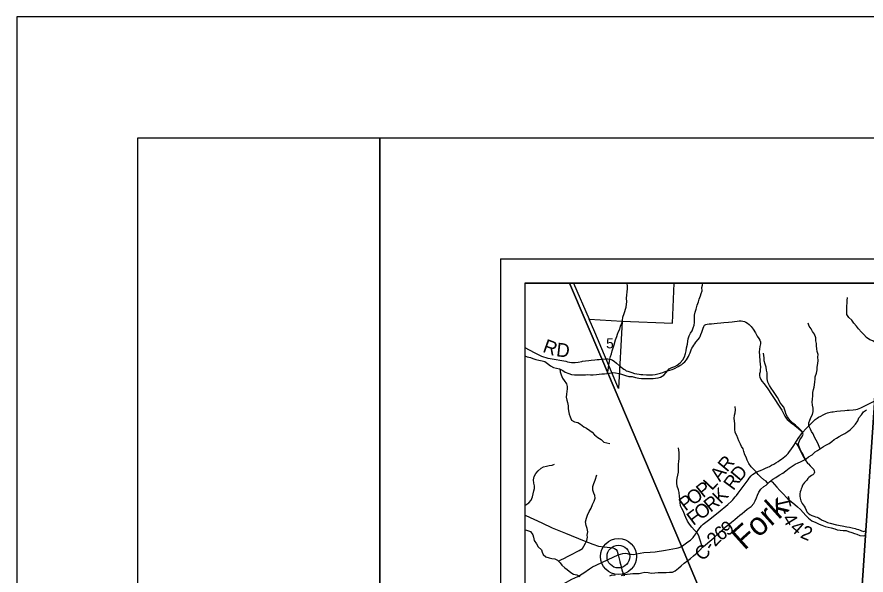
# Model space of a CAD drawing. Extents: x 0 to 34, y 0 to 22.
# Drawn here: x 0 to 3.511, y 19.693 to 22 of the extents above; entities that cross this region are included whole.
import ezdxf

# ---------------------------------------------------------------- set-up
doc = ezdxf.new("R2010")
doc.units = 0
for name, color, linetype in [('GM_X_County_Road', 7, 'Continuous'), ('GM_X_County_Road_Text', 7, 'Continuous'), ('GM_X_Minor_River', 7, 'Continuous'), ('GM_X_Minor_River_Text', 7, 'Continuous'), ('GM_X_Section', 7, 'Continuous'), ('GM_X_Section_Text', 7, 'Continuous'), ('GM_X_State_Route', 7, 'Continuous'), ('GM_X_Township_Road', 7, 'Continuous'), ('GM_X_Township_Road_Text', 7, 'Continuous'), ('GM_X_Unincorporated', 7, 'Continuous'), ('GM_X_Unincorporated_Location', 7, 'Continuous'), ('SH_Border', 7, 'Continuous'), ('SH_Cut_Line', 7, 'Continuous'), ('SH_Data', 7, 'Continuous')]:
    doc.layers.add(name, color=color, linetype=linetype)

msp = doc.modelspace()

# ---------------------------------------------------------------- linework, layer by layer
at = {"layer": 'GM_X_County_Road'}
for points in [[(2.7739, 19.8298), (2.7851, 19.8379), (2.7904, 19.8427), (2.7958, 19.8477), (2.7994, 19.8521), (2.803, 19.8578), (2.8067, 19.8636), (2.8095, 19.8687), (2.8193, 19.8833), (2.8246, 19.8903), (2.8306, 19.8969), (2.8369, 19.9032), (2.8588, 19.9195), (2.8997, 19.952), (2.9396, 19.985), (2.9543, 19.9983), (2.96, 20.0037), (2.9648, 20.0096), (2.9696, 20.0159), (2.9749, 20.0226), (2.9827, 20.0323), (3.023, 20.0866), (3.0278, 20.0931), (3.0364, 20.103), (3.0419, 20.1082), (3.0477, 20.113), (3.0538, 20.117), (3.0603, 20.1203), (3.0662, 20.1222), (3.075, 20.1258), (3.0863, 20.1303), (3.0951, 20.1346), (3.1045, 20.139), (3.1112, 20.1423), (3.1197, 20.1469), (3.1294, 20.1519), (3.1384, 20.1572), (3.1479, 20.1629), (3.1545, 20.1674), (3.1614, 20.1727), (3.1685, 20.1779), (3.1752, 20.1831), (3.1819, 20.189), (3.1884, 20.1961), (3.1945, 20.2032), (3.1999, 20.2105), (3.2126, 20.2285), (3.2196, 20.2395), (3.2308, 20.2572), (3.2475, 20.282), (3.2635, 20.2983), (3.2932, 20.3292), (3.3011, 20.3364), (3.3086, 20.3416), (3.3149, 20.3453), (3.3233, 20.3506), (3.3342, 20.3561), (3.3396, 20.3586), (3.3446, 20.3609), (3.3513, 20.3634), (3.3626, 20.3666), (3.3689, 20.3674), (3.375, 20.3682), (3.3903, 20.3703), (3.4054, 20.372), (3.4234, 20.3735), (3.4328, 20.3743), (3.4417, 20.3744), (3.4575, 20.3756), (3.4686, 20.377), (3.4755, 20.3785), (3.4826, 20.381), (3.4893, 20.3844), (3.5465, 20.4139)], [(2.4861, 19.7772), (2.5054, 19.7827), (2.5157, 19.7836), (2.5234, 19.782), (2.5314, 19.7801), (2.5403, 19.779), (2.5509, 19.7784), (2.5617, 19.7802), (2.5926, 19.786), (2.6179, 19.7872), (2.6393, 19.7886), (2.682, 19.7958), (2.7265, 19.8042), (2.7338, 19.806), (2.7416, 19.8088), (2.7475, 19.8116), (2.757, 19.8176), (2.7739, 19.8298)], [(2.1, 19.577), (2.1629, 19.6015), (2.1807, 19.6078), (2.1964, 19.6157), (2.2092, 19.6227), (2.2498, 19.6515), (2.2594, 19.6574), (2.2946, 19.6756), (2.3185, 19.6871), (2.3444, 19.7028), (2.3667, 19.7187), (2.3804, 19.7267), (2.3947, 19.7344), (2.4447, 19.7581), (2.4861, 19.7772)]]:
    msp.add_lwpolyline(points, dxfattribs=at)
at = {"layer": 'GM_X_Minor_River'}
for points in [[(2.4417, 20.5269), (2.4447, 20.5405), (2.4455, 20.55), (2.4467, 20.5621), (2.4495, 20.5754), (2.4511, 20.5852), (2.4546, 20.597), (2.4581, 20.6075), (2.4612, 20.6204), (2.4647, 20.6318), (2.4697, 20.6446), (2.4752, 20.6651), (2.4806, 20.6791), (2.4837, 20.6889), (2.4879, 20.6995), (2.4926, 20.7101), (2.4961, 20.7226), (2.5007, 20.7347), (2.5034, 20.7449), (2.5058, 20.7596), (2.5101, 20.774), (2.5186, 20.8005), (2.5206, 20.8126), (2.5211, 20.8221), (2.5204, 20.838), (2.5217, 20.8498), (2.5233, 20.8634), (2.5242, 20.8763), (2.5239, 20.8877), (2.5236, 20.898), (2.5239, 20.9)], [(2.558, 20.51), (2.5708, 20.5073), (2.5829, 20.5061), (2.5969, 20.5056), (2.6072, 20.5059), (2.62, 20.5054), (2.631, 20.5057), (2.6408, 20.5064), (2.6507, 20.5078), (2.6613, 20.5111), (2.675, 20.5198), (2.6838, 20.5307), (2.6972, 20.5454), (2.7078, 20.551), (2.7203, 20.5554), (2.7299, 20.561), (2.7428, 20.5708), (2.7527, 20.5825), (2.76, 20.5946), (2.7639, 20.6093), (2.767, 20.6203), (2.769, 20.6324), (2.7722, 20.6472), (2.7742, 20.6601), (2.7754, 20.6695), (2.7793, 20.6824), (2.7854, 20.6926), (2.7912, 20.7028), (2.7962, 20.7149), (2.7997, 20.7259), (2.802, 20.7376), (2.8021, 20.7471), (2.8018, 20.7566), (2.8015, 20.7676), (2.8046, 20.7804), (2.8081, 20.7925), (2.8124, 20.8088), (2.8182, 20.8224), (2.8213, 20.833), (2.8267, 20.847), (2.8295, 20.8569), (2.8326, 20.8686), (2.8319, 20.8819), (2.8339, 20.8917), (2.8354, 20.9)], [(3.563, 20.6475), (3.5501, 20.6536), (3.5384, 20.6616), (3.5263, 20.6655), (3.5128, 20.6751), (3.5019, 20.6873), (3.4918, 20.6977), (3.479, 20.7114), (3.4707, 20.7213), (3.4602, 20.7339), (3.4516, 20.7469), (3.4396, 20.7584), (3.4318, 20.7706), (3.4311, 20.7827), (3.4312, 20.7956), (3.4309, 20.8059), (3.4321, 20.8165), (3.433, 20.8286), (3.4338, 20.8411)], [(3.3217, 20.2151), (3.3165, 20.2246), (3.3117, 20.2379), (3.3046, 20.2505), (3.2983, 20.2634), (3.292, 20.2771), (3.2849, 20.2866), (3.2808, 20.2965), (3.2748, 20.3095), (3.2749, 20.3227), (3.278, 20.3333), (3.2834, 20.347), (3.2896, 20.3571), (3.2916, 20.3689), (3.2924, 20.3825), (3.2891, 20.3955), (3.2885, 20.4087), (3.2901, 20.419), (3.2906, 20.4349), (3.2914, 20.4482), (3.2934, 20.4595), (3.2962, 20.4697), (3.2977, 20.48), (3.299, 20.4921), (3.3002, 20.5035), (3.3007, 20.5129), (3.3053, 20.5281), (3.3081, 20.5417), (3.3093, 20.5527), (3.3121, 20.5675), (3.3122, 20.5807), (3.3108, 20.5944), (3.3131, 20.6042), (3.3083, 20.6179), (3.3076, 20.6278), (3.3066, 20.6403), (3.3055, 20.6502), (3.3037, 20.6612), (3.3034, 20.6741), (3.2983, 20.6882), (3.2893, 20.7), (3.2833, 20.7103), (3.2751, 20.7225), (3.2714, 20.735)], [(3.2601, 20.172), (3.2545, 20.1811), (3.2489, 20.1944), (3.243, 20.2043), (3.2381, 20.2138), (3.2333, 20.2271), (3.2322, 20.2374), (3.2376, 20.2514), (3.2442, 20.2623), (3.2511, 20.2744), (3.2466, 20.2869), (3.232, 20.3011), (3.2185, 20.313), (3.2079, 20.3214), (3.1959, 20.3329), (3.1865, 20.347), (3.1806, 20.3572), (3.1769, 20.3702), (3.1706, 20.3865), (3.1623, 20.3972), (3.1545, 20.4083), (3.1504, 20.4178), (3.1448, 20.4277), (3.1362, 20.4388), (3.1283, 20.4513), (3.1186, 20.4662), (3.1111, 20.4765), (3.1044, 20.491), (3.1019, 20.5039), (3.1019, 20.5145), (3.1017, 20.5285), (3.0999, 20.5403), (3.0977, 20.5525), (3.094, 20.5646), (3.0896, 20.5783), (3.0893, 20.5908), (3.0872, 20.6098)], [(2.1, 20.5988), (2.1101, 20.5951), (2.1229, 20.592), (2.1335, 20.5877), (2.1448, 20.5842), (2.1573, 20.5818), (2.1713, 20.5787), (2.1822, 20.5756), (2.1939, 20.5671), (2.2056, 20.5576), (2.218, 20.551), (2.2305, 20.5487), (2.2433, 20.5455), (2.2573, 20.5386), (2.2674, 20.5317), (2.2814, 20.5263), (2.2927, 20.5228), (2.3052, 20.5211), (2.3154, 20.5203), (2.3362, 20.5201), (2.3503, 20.5212), (2.3601, 20.5218), (2.3715, 20.5214), (2.382, 20.5205), (2.3968, 20.5227), (2.4071, 20.5238), (2.418, 20.5244), (2.429, 20.5255), (2.4396, 20.5265), (2.4495, 20.5283), (2.4639, 20.5298), (2.4745, 20.5297), (2.49, 20.5265), (2.5036, 20.5226), (2.5168, 20.5183), (2.5304, 20.5144), (2.544, 20.514), (2.558, 20.51)], [(2.2445, 20.5449), (2.2466, 20.5326), (2.2507, 20.5208), (2.2555, 20.5067), (2.263, 20.4972), (2.2716, 20.4842), (2.2746, 20.4728), (2.2745, 20.463), (2.2736, 20.452), (2.272, 20.4414), (2.2712, 20.4289), (2.2741, 20.4163), (2.2767, 20.4061), (2.2785, 20.3932), (2.2791, 20.3822), (2.2806, 20.3723), (2.2839, 20.3575), (2.2868, 20.3472), (2.2935, 20.3339), (2.3059, 20.3262), (2.3195, 20.3231), (2.3305, 20.3169), (2.3444, 20.3065), (2.3553, 20.3004), (2.3685, 20.2908), (2.3783, 20.2835), (2.388, 20.2721), (2.402, 20.2613), (2.4151, 20.254), (2.4268, 20.2429), (2.4389, 20.2391), (2.4514, 20.2371)], [(2.8123, 19.7852), (2.8237, 19.7961), (2.8352, 19.8078), (2.8451, 19.8168), (2.8569, 19.8262), (2.8725, 19.8405), (2.8821, 19.8476), (2.8939, 19.8597), (2.9068, 19.871), (2.9171, 19.8807), (2.9282, 19.8916), (2.9389, 19.8999), (2.9549, 19.9111), (2.9686, 19.9224), (2.9793, 19.933), (2.9895, 19.9408), (2.9991, 19.9476), (3.0086, 19.9555), (3.0196, 19.9649), (3.0352, 19.9761), (3.0463, 19.9889), (3.0521, 19.9995), (3.0579, 20.012), (3.0621, 20.0229), (3.0675, 20.0354), (3.0759, 20.0486), (3.0878, 20.0591), (3.098, 20.0651), (3.1114, 20.0779), (3.1251, 20.0892), (3.1376, 20.0959), (3.1517, 20.1057), (3.1669, 20.1146), (3.1795, 20.1233), (3.1928, 20.1345), (3.205, 20.1428), (3.2179, 20.1514), (3.2297, 20.1574), (3.2396, 20.1615), (3.2506, 20.1663), (3.2632, 20.1738), (3.2731, 20.1821), (3.2879, 20.1903), (3.3005, 20.2019), (3.3107, 20.2083), (3.3229, 20.2158), (3.3355, 20.2248), (3.345, 20.2304), (3.3587, 20.2371), (3.3697, 20.2458), (3.3792, 20.2533), (3.3887, 20.2593), (3.4001, 20.266), (3.4127, 20.2731), (3.423, 20.2783), (3.4355, 20.2866), (3.445, 20.2941), (3.4565, 20.3043), (3.4675, 20.3163), (3.4764, 20.3303), (3.481, 20.3427), (3.4917, 20.3552), (3.5009, 20.3684), (3.5131, 20.3766)], [(3.1052, 20.072), (3.0978, 20.0807), (3.0876, 20.0868), (3.0741, 20.0991), (3.0651, 20.1086), (3.0568, 20.1193), (3.0448, 20.1304), (3.0358, 20.1399), (3.026, 20.1544), (3.019, 20.1678), (3.0153, 20.1803), (3.0097, 20.1902), (3.0052, 20.2039), (3.0023, 20.2149), (2.9963, 20.2244), (2.9919, 20.234), (2.9848, 20.2477), (2.9807, 20.2595), (2.9759, 20.2697), (2.9703, 20.2823), (2.9685, 20.2956), (2.9682, 20.3066), (2.9683, 20.3176), (2.9673, 20.3301), (2.9662, 20.3403), (2.9667, 20.3536), (2.969, 20.3638), (2.971, 20.3767), (2.9696, 20.3892)], [(2.8341, 19.8067), (2.8304, 19.82), (2.8267, 19.8329), (2.8219, 19.8451), (2.8189, 19.855), (2.8129, 19.8671), (2.8021, 19.879), (2.7908, 19.8908), (2.7807, 19.9038), (2.7725, 19.9164), (2.7661, 19.9308), (2.7613, 19.9411), (2.7565, 19.9552), (2.7486, 19.9689), (2.7438, 19.9795), (2.7416, 19.9936), (2.7406, 20.008), (2.7396, 20.0179), (2.7382, 20.0342), (2.7356, 20.046), (2.7301, 20.0601), (2.7279, 20.073), (2.7287, 20.0836), (2.7299, 20.0942), (2.7323, 20.1059), (2.7347, 20.1184), (2.7355, 20.1286), (2.736, 20.1393), (2.7357, 20.151), (2.7369, 20.1631), (2.7378, 20.1753), (2.7386, 20.1863), (2.7387, 20.1999), (2.7369, 20.2094), (2.7355, 20.2193)], [(2.1, 19.9809), (2.1045, 19.9834), (2.1159, 19.9913), (2.1255, 20.0022), (2.1316, 20.0162), (2.134, 20.0295), (2.1375, 20.0412), (2.1403, 20.051), (2.1396, 20.0617), (2.1366, 20.0731), (2.1356, 20.0863), (2.1384, 20.1), (2.146, 20.1128), (2.1548, 20.1237), (2.167, 20.1343), (2.1773, 20.1406), (2.1894, 20.1436), (2.2, 20.1454), (2.2126, 20.1475), (2.2224, 20.1513)], [(2.2398, 19.7499), (2.2484, 19.7555), (2.2636, 19.7626), (2.2762, 19.7705), (2.2895, 19.7768), (2.3013, 19.782), (2.3108, 19.7873), (2.3252, 19.7951), (2.3382, 19.8034), (2.3439, 19.8132), (2.3512, 19.8256), (2.3566, 19.8366), (2.3586, 19.8491), (2.3579, 19.8586), (2.3603, 19.8722), (2.3581, 19.8851), (2.3529, 19.8973), (2.3511, 19.9125), (2.3547, 19.9288), (2.3597, 19.9409), (2.3666, 19.956), (2.3739, 19.9699), (2.3797, 19.9851), (2.387, 19.9987), (2.3909, 20.0115), (2.3895, 20.0225), (2.3846, 20.032), (2.3806, 20.0446), (2.3814, 20.0594), (2.3846, 20.0719), (2.3907, 20.0847), (2.397, 20.1074)], [(3.1153, 20.0811), (3.1224, 20.079), (3.1325, 20.0679), (3.1422, 20.0561), (3.1542, 20.0431), (3.1636, 20.0331), (3.188, 20.0083), (3.2012, 19.9968), (3.2166, 19.9842), (3.2279, 19.975), (3.2392, 19.9639), (3.2508, 19.9517), (3.2617, 19.9398), (3.2729, 19.9276), (3.2873, 19.9176), (3.3038, 19.9099), (3.317, 19.9037), (3.3276, 19.8995), (3.3416, 19.8933), (3.3544, 19.8909), (3.3673, 19.8882), (3.3812, 19.8839), (3.391, 19.8804), (3.4035, 19.878), (3.4168, 19.8772), (3.4281, 19.8771), (3.4387, 19.8736), (3.4519, 19.8686), (3.4632, 19.8654), (3.473, 19.8623), (3.4855, 19.8573), (3.5002, 19.8557), (3.5096, 19.858)], [(2.1, 19.8799), (2.1071, 19.8787), (2.1233, 19.8729), (2.1331, 19.8596), (2.1353, 19.8497), (2.1386, 19.836), (2.1479, 19.8215), (2.155, 19.8094), (2.1685, 19.7967), (2.1715, 19.7872), (2.1763, 19.7777), (2.1872, 19.7685), (2.2001, 19.7643), (2.2122, 19.7611), (2.2246, 19.7595), (2.2352, 19.7541), (2.2465, 19.7438), (2.2524, 19.7343), (2.2656, 19.7228), (2.2754, 19.7155), (2.2897, 19.704), (2.3017, 19.6971), (2.3146, 19.6936), (2.3274, 19.687)], [(2.4997, 19.6914), (2.5137, 19.6951), (2.5232, 19.6969), (2.5361, 19.6987), (2.5467, 19.6997), (2.5603, 19.6992), (2.5724, 19.6991), (2.5834, 19.7021), (2.5967, 19.7054), (2.6103, 19.7038), (2.6243, 19.7014), (2.6379, 19.7024), (2.6508, 19.7038), (2.6614, 19.7038), (2.6743, 19.704), (2.6841, 19.7043), (2.6977, 19.7046), (2.7102, 19.7056), (2.722, 19.7109), (2.735, 19.7218), (2.7468, 19.7311), (2.759, 19.7417), (2.7742, 19.7537), (2.7845, 19.7619), (2.7974, 19.7732), (2.8123, 19.7852)], [(2.4508, 19.6899), (2.4607, 19.6936), (2.4732, 19.692)]]:
    msp.add_lwpolyline(points, dxfattribs=at)
at = {"layer": 'GM_X_Section'}
msp.add_lwpolyline([(2.3659, 20.7513), (2.503, 20.7433), (2.4876, 20.4641), (2.389, 20.6968)], close=True, dxfattribs=at)
at = {"layer": 'GM_X_State_Route'}
for points in [[(2.1, 19.941), (2.1034, 19.9394), (2.1698, 19.9084), (2.2134, 19.8884), (2.2678, 19.8659), (2.3446, 19.8344), (2.3806, 19.8207), (2.4047, 19.8132), (2.4274, 19.8097), (2.4528, 19.8071), (2.4635, 19.8056), (2.4713, 19.803), (2.478, 19.7983), (2.4822, 19.7921), (2.4861, 19.7772), (2.4931, 19.7488)], [(2.4931, 19.7488), (2.4934, 19.7478), (2.4978, 19.7287), (2.5012, 19.7143), (2.5062, 19.6989), (2.5108, 19.6893)]]:
    msp.add_lwpolyline(points, dxfattribs=at)
at = {"layer": 'GM_X_Township_Road'}
for points in [[(2.4919, 20.5579), (2.5092, 20.5439), (2.5142, 20.5408), (2.519, 20.538), (2.5253, 20.5353), (2.5335, 20.5326), (2.5421, 20.5301), (2.5538, 20.5269), (2.5634, 20.5251), (2.5729, 20.5238), (2.5793, 20.5225), (2.5881, 20.5219), (2.6032, 20.5213), (2.617, 20.5207), (2.6277, 20.5205), (2.6388, 20.5217), (2.6503, 20.5244), (2.6612, 20.5278), (2.6704, 20.5309), (2.6801, 20.5345), (2.6889, 20.537), (2.6993, 20.5399), (2.7085, 20.5435), (2.7188, 20.5475), (2.7335, 20.5548), (2.7412, 20.5588), (2.7492, 20.5638), (2.7552, 20.5684), (2.7617, 20.5747), (2.7682, 20.5826), (2.7728, 20.5893), (2.7768, 20.596), (2.7801, 20.6034), (2.7835, 20.6111), (2.7879, 20.6239), (2.7908, 20.631), (2.794, 20.6364), (2.7982, 20.6434), (2.8028, 20.6492), (2.8074, 20.6559), (2.8164, 20.6664), (2.8216, 20.6731), (2.8254, 20.6792), (2.8283, 20.6869), (2.8317, 20.6972), (2.834, 20.706), (2.8367, 20.7135), (2.8398, 20.7202), (2.8427, 20.7254), (2.8482, 20.7292), (2.8538, 20.7309), (2.8622, 20.7315), (2.8719, 20.7319), (2.8832, 20.7326), (2.8949, 20.734), (2.91, 20.7355), (2.9232, 20.7367), (2.9418, 20.7388), (2.9569, 20.7403), (2.9671, 20.7411), (2.9778, 20.7426), (2.9866, 20.7434), (2.9945, 20.7434), (3.0017, 20.7424), (3.0088, 20.7407), (3.0144, 20.738), (3.0207, 20.7346), (3.028, 20.7284), (3.0352, 20.721), (3.0442, 20.7095), (3.0534, 20.6947), (3.0609, 20.6806), (3.0672, 20.6708), (3.0712, 20.6641), (3.0741, 20.6566), (3.0745, 20.6492), (3.072, 20.6383), (3.0703, 20.6262), (3.0693, 20.6153), (3.0699, 20.6011), (3.0722, 20.5772), (3.0741, 20.5525), (3.0737, 20.5412), (3.0726, 20.5336), (3.0708, 20.5251), (3.0697, 20.5173), (3.071, 20.5108), (3.0756, 20.5016), (3.0806, 20.4943), (3.089, 20.4836), (3.1041, 20.4635), (3.12, 20.4398), (3.1627, 20.3743), (3.1744, 20.3506), (3.1801, 20.3419), (3.1849, 20.3366), (3.192, 20.3301), (3.2018, 20.3224), (3.2144, 20.3123), (3.2267, 20.3033), (3.2475, 20.282)], [(2.1, 20.6334), (2.1388, 20.6126), (2.1627, 20.6004), (2.169, 20.5979), (2.1771, 20.5952), (2.1866, 20.5925), (2.1953, 20.5902), (2.2048, 20.5883), (2.2691, 20.5766), (2.2768, 20.5745), (2.285, 20.5734), (2.2933, 20.5715), (2.3011, 20.5718), (2.3084, 20.5722), (2.3199, 20.5738), (2.3359, 20.5763)], [(2.3359, 20.5763), (2.3388, 20.5768), (2.3503, 20.5782), (2.3645, 20.5805), (2.3744, 20.5816), (2.3894, 20.5828), (2.3991, 20.5837), (2.4077, 20.5847), (2.4182, 20.586), (2.4378, 20.587), (2.443, 20.5866)], [(2.443, 20.5866), (2.45, 20.5856), (2.4571, 20.5837), (2.4623, 20.5814), (2.4692, 20.5772), (2.4784, 20.5688), (2.4919, 20.5579)], [(3.2196, 20.2395), (3.2238, 20.2357), (3.2293, 20.2271), (3.251, 20.1836), (3.2572, 20.1725), (3.2615, 20.1656), (3.2661, 20.1601), (3.2693, 20.1561), (3.2724, 20.1524), (3.2799, 20.145), (3.2871, 20.1375), (3.2929, 20.1308), (3.2967, 20.1245), (3.2975, 20.1191), (3.2965, 20.1147), (3.2944, 20.1109), (3.2904, 20.1076), (3.2856, 20.1042), (3.2804, 20.1004), (3.2749, 20.0967), (3.2697, 20.0916), (3.2655, 20.086), (3.2605, 20.0801), (3.2563, 20.0755), (3.2521, 20.0707), (3.2485, 20.0651), (3.2448, 20.0548), (3.2429, 20.0491), (3.2406, 20.0445), (3.2383, 20.0366), (3.2368, 20.0295), (3.2364, 20.0198), (3.2381, 20.0104), (3.2414, 19.9999), (3.2462, 19.9895), (3.2515, 19.983), (3.255, 19.9782), (3.2594, 19.9704), (3.2634, 19.9612), (3.2663, 19.9549), (3.2718, 19.9495), (3.2783, 19.9432), (3.286, 19.9392), (3.2902, 19.9375), (3.295, 19.9359), (3.3025, 19.9338), (3.3086, 19.9319), (3.3143, 19.9294), (3.3206, 19.9252), (3.3298, 19.9204), (3.3398, 19.9162), (3.3515, 19.9107), (3.3622, 19.9076), (3.388, 19.9009), (3.4116, 19.8961), (3.4311, 19.8929), (3.442, 19.8913), (3.4539, 19.8881), (3.4665, 19.885), (3.4728, 19.8831), (3.4797, 19.8808), (3.4864, 19.8783), (3.4922, 19.8754), (3.4971, 19.8739), (3.5008, 19.8737), (3.5048, 19.8745), (3.5102, 19.8764)]]:
    msp.add_lwpolyline(points, dxfattribs=at)
at = {"layer": 'GM_X_Township_Road_Text'}
msp.add_lwpolyline([(2.7177, 20.9), (2.3012, 20.9), (2.3659, 20.7513), (2.503, 20.7433), (2.7106, 20.7339)], close=True, dxfattribs=at)
at = {"layer": 'GM_X_Unincorporated'}
for points in [[(2.2853, 20.9), (2.1, 20.9), (2.1, 14.1), (2.8399, 14.1), (2.9778, 14.1609), (3.8099, 14.5285), (4.2904, 14.7408), (4.3998, 14.7897), (4.802, 14.9692), (4.4847, 15.685), (4.2937, 16.1161), (4.0882, 16.6114), (3.972, 16.8916), (3.7367, 17.4136), (3.709, 17.484), (3.4011, 18.2653), (3.1249, 18.9173), (3.0781, 19.0279), (2.9956, 19.2227), (2.9553, 19.318), (2.7473, 19.8121), (2.418, 20.5866)], [(6.769, 20.9), (2.2853, 20.9), (2.418, 20.5866), (2.7473, 19.8121), (2.9553, 19.318), (2.9956, 19.2227), (3.0781, 19.0279), (3.1249, 18.9173), (3.4011, 18.2653), (3.4595, 19.1305), (3.4599, 19.1361), (3.5099, 19.8769), (3.5456, 20.4047), (3.5457, 20.4056), (3.5462, 20.4144), (3.5651, 20.6937), (3.8602, 20.6728), (4.3099, 20.6409), (6.6484, 20.4847), (6.6568, 20.5136)]]:
    msp.add_lwpolyline(points, close=True, dxfattribs=at)
msp.add_lwpolyline([(3.5456, 20.4047), (3.5099, 19.8769), (3.4599, 19.1361), (3.4595, 19.1305), (3.4011, 18.2653), (3.709, 17.484)], dxfattribs=at)
for radius in [0.0744, 0.0472]:
    msp.add_circle((2.487, 19.7697), radius, dxfattribs=at)
at = {"layer": 'GM_X_Unincorporated_Location'}
msp.add_line((2.487, 19.7697), (2.487, 19.7697), dxfattribs=at)
at = {"layer": 'SH_Border'}
for points in [[(0.5, 21.5), (1.5, 21.5), (1.5, 0.5), (0.5, 0.5)], [(1.5, 21.5), (33.5, 21.5), (33.5, 0.5), (1.5, 0.5)]]:
    msp.add_lwpolyline(points, close=True, dxfattribs=at)
at = {"layer": 'SH_Cut_Line'}
msp.add_lwpolyline([(0, 0), (34, 0), (34, 22), (0, 22)], close=True, dxfattribs=at)
for points in [[(4.2937, 16.1161), (4.0882, 16.6114), (3.972, 16.8916), (3.7367, 17.4136), (3.709, 17.484), (3.4011, 18.2653), (3.4595, 19.1305), (3.4599, 19.1361), (3.5099, 19.8769), (3.5456, 20.4047), (3.5457, 20.4056), (3.5462, 20.4144), (3.5651, 20.6937), (3.8602, 20.6728), (4.3099, 20.6409), (6.6484, 20.4847), (6.6568, 20.5136), (6.769, 20.9), (2.1, 20.9), (2.1, 14.1)], [(8.9, 14.1), (8.9, 20.9), (6.769, 20.9), (6.6568, 20.5136), (6.6484, 20.4847), (4.3099, 20.6409), (3.8602, 20.6728), (3.5651, 20.6937), (3.5462, 20.4144), (3.5457, 20.4056), (3.5456, 20.4047), (3.5099, 19.8769), (3.4599, 19.1361), (3.4595, 19.1305), (3.4011, 18.2653), (3.709, 17.484), (3.7367, 17.4136), (3.972, 16.8916), (4.0882, 16.6114), (4.2937, 16.1161)]]:
    msp.add_lwpolyline(points, dxfattribs=at)
at = {"layer": 'SH_Data'}
for p, q in [((2, 21), (9, 21)), ((2, 21), (2, 14)), ((2.1, 20.9), (2.1, 14.1)), ((2.1, 20.9), (8.9, 20.9))]:
    msp.add_line(p, q, dxfattribs=at)

# ---------------------------------------------------------------- texts
at = {"layer": 'GM_X_County_Road_Text'}
for s, rotation, p in [('R', 50.2149, (2.9361, 20.1158)), ('A', 53.4542, (2.9068, 20.0763)), ('D', 49.7282, (2.9892, 20.0765)), ('L', 46.7505, (2.873, 20.0398)), ('R', 53.7697, (2.9623, 20.0397)), ('O', 36.1515, (2.7943, 19.9786)), ('P', 39.0149, (2.8371, 20.01)), ('K', 45.1103, (2.9096, 19.9838)), ('P', 37.5151, (2.7642, 19.9555)), ('R', 38.7902, (2.8682, 19.95)), ('O', 37.4437, (2.8273, 19.9187)), ('F', 37.2899, (2.7967, 19.8954)), ('9', 36.1517, (2.9373, 19.8522)), ('6', 36.2152, (2.9091, 19.8315)), ('2', 46.5567, (2.887, 19.8079)), ('C', 44.8082, (2.8347, 19.7481)), ('-', 56.22, (2.8756, 19.7905))]:
    msp.add_text(s, height=0.0568, rotation=rotation, dxfattribs=at).set_placement(p)
at = {"layer": 'GM_X_Minor_River_Text'}
msp.add_text('Fork', height=0.09469, rotation=41.9992, dxfattribs=at).set_placement((3.0077, 19.7927))
at = {"layer": 'GM_X_Section_Text'}
msp.add_text('5', height=0.0419, rotation=0, dxfattribs=at).set_placement((2.4361, 20.6301))
at = {"layer": 'GM_X_Township_Road_Text'}
for s, rotation, p in [('R', 340.3992, (2.1703, 20.6166)), ('D', 353.358, (2.2277, 20.5978)), ('T', 282.8663, (3.1367, 20.0086)), ('-', 290.757, (3.1486, 19.9591)), ('4', 301.8595, (3.1622, 19.9265)), ('4', 318.581, (3.1923, 19.883)), ('2', 337.3121, (3.2356, 19.8492))]:
    msp.add_text(s, height=0.0568, rotation=rotation, dxfattribs=at).set_placement(p)

doc.saveas('drawing.dxf')
